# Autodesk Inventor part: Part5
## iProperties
Shininess: 64.0
Length Units: 11269
Angle Units: 11279
Time Units: 11290
Mass Units: 11283
Length Display Precision: 3
Angle Display Precision: 2
Compacted: True
Part Number: Part5
Document SubType Name: Modeling
Created: 2004-08
Designer: John Blackburn
Manufacturer: Standard
Standards Organization: Custom
Density: 0.0
Volumn: 0.0
Area: 0.0
PropertySet Name: Model Information
Control State: 0
Master: False
Checked Out: False
Author: John Blackburn
